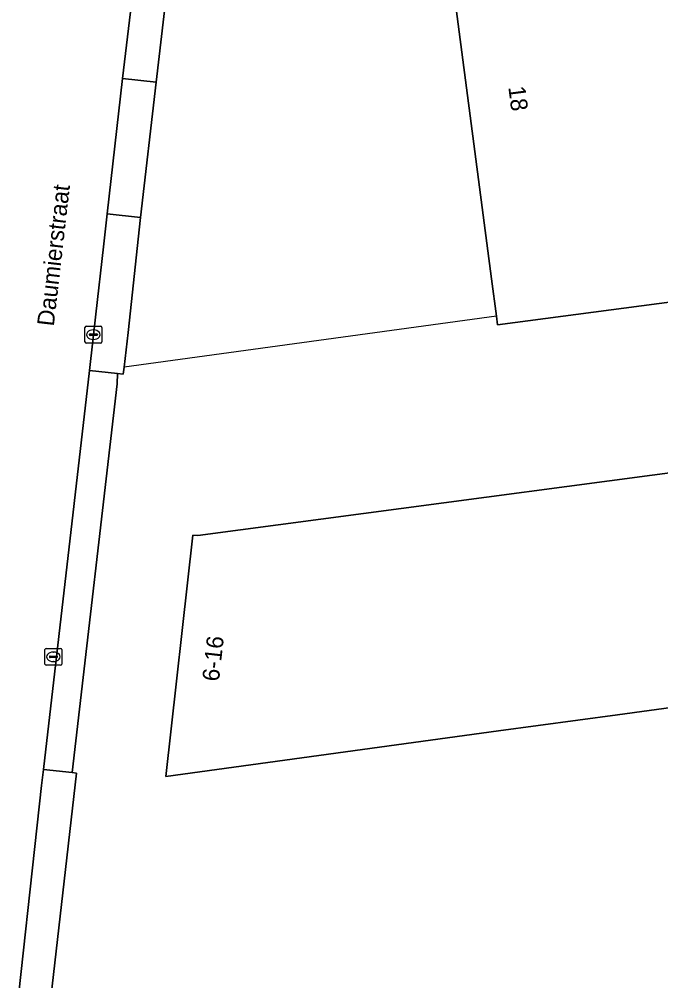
# Model space of a CAD drawing. Extents: x 160554 to 161248, y 385329 to 386506.
# Drawn here: x 161027.9 to 161065.9, y 385731.1 to 385787.9 of the extents above; entities that cross this region are included whole.
import ezdxf

# ---------------------------------------------------------------- set-up
doc = ezdxf.new("R2010")
doc.units = 0
for name, color, linetype in [('IMGEO_Erf', 7, 'Continuous'), ('IMGEO_Hek', 7, 'Continuous'), ('IMGEO_Kolk', 7, 'Continuous'), ('IMGEO_Openbare_ruimte_label', 7, 'Continuous'), ('IMGEO_Pand', 7, 'Continuous'), ('IMGEO_Pand_nummerreeks', 7, 'Continuous'), ('IMGEO_Rijbaan_lokaal_gesloten', 7, 'Continuous'), ('IMGEO_Voetpad_open', 7, 'Continuous')]:
    doc.layers.add(name, color=color, linetype=linetype)

msp = doc.modelspace()

# ---------------------------------------------------------------- linework, layer by layer
at = {"layer": 'IMGEO_Erf'}
for points in [[(161055.868, 385772.603), (161052.902, 385795.197), (161048.55, 385828.073), (161045.239, 385827.611), (161043.376, 385821.859)], [(161038.935, 385804.639), (161037.917, 385798.744), (161037.106, 385793.587), (161037.068, 385793.188), (161036.035, 385784.231), (161035.112, 385776.221), (161034.38, 385769.433), (161034.13, 385767.378), (161034.079, 385766.959), (161033.737, 385767.013), (161033.718, 385766.391), (161031.068, 385743.412), (161031.33, 385743.384), (161029.381, 385726.474), (161028.228, 385716.42), (161027.96, 385714.08)], [(161076.078, 385772.498), (161056.219, 385769.879), (161056.153, 385770.395), (161055.868, 385772.603)], [(161094.436, 385751.08), (161063.317, 385746.837), (161056.279, 385745.877), (161036.601, 385743.194), (161038.201, 385757.455), (161038.492, 385757.432), (161077.384, 385762.597)]]:
    msp.add_lwpolyline(points, dxfattribs=at)
at = {"layer": 'IMGEO_Hek'}
msp.add_lwpolyline([(161056.153, 385770.395), (161034.13, 385767.378)], dxfattribs=at)
at = {"layer": 'IMGEO_Kolk'}
for p, q in [((161031.821, 385768.871), (161031.821, 385769.723)), ((161031.896, 385769.797), (161032.748, 385769.797)), ((161032.08, 385769.291), (161032.08, 385769.303)), ((161032.518, 385769.254), (161032.12, 385769.254)), ((161032.123, 385769.34), (161032.521, 385769.34)), ((161032.309, 385769.577), (161032.334, 385769.577)), ((161032.564, 385769.303), (161032.564, 385769.291)), ((161032.822, 385769.723), (161032.822, 385768.871)), ((161032.748, 385768.797), (161031.896, 385768.797)), ((161032.332, 385769.017), (161032.307, 385769.017)), ((161029.456, 385749.833), (161029.456, 385750.685)), ((161029.531, 385750.759), (161030.383, 385750.759)), ((161029.944, 385750.539), (161029.969, 385750.539)), ((161030.457, 385750.685), (161030.457, 385749.833)), ((161029.715, 385750.253), (161029.715, 385750.265)), ((161030.153, 385750.216), (161029.755, 385750.216)), ((161029.758, 385750.302), (161030.156, 385750.302)), ((161029.967, 385749.979), (161029.942, 385749.979)), ((161030.199, 385750.265), (161030.199, 385750.253)), ((161030.383, 385749.759), (161029.531, 385749.759))]:
    msp.add_line(p, q, dxfattribs=at)
for points in [[(161031.821, 385768.871), (161031.821, 385769.723)], [(161031.896, 385769.797), (161032.748, 385769.797)], [(161032.822, 385769.723), (161032.822, 385768.871)], [(161032.748, 385768.797), (161031.896, 385768.797)], [(161029.456, 385749.833), (161029.456, 385750.685)], [(161029.531, 385750.759), (161030.383, 385750.759)], [(161030.457, 385750.685), (161030.457, 385749.833)], [(161030.383, 385749.759), (161029.531, 385749.759)]]:
    msp.add_lwpolyline(points, dxfattribs=at)
for centre, radius, start, end in [((161031.898, 385769.721), 0.0765, 91.552, 178.448), ((161031.898, 385769.721), 0.0765, 91.552, 178.448), ((161032.12, 385769.3), 0.0403, 85.8775, 175.7526), ((161032.117, 385769.29), 0.0366, 178.938, 274.7102), ((161032.521, 385769.297), 0.043, 264.8664, 352.4533), ((161032.525, 385769.302), 0.0386, 1.7309, 96.639), ((161032.746, 385769.721), 0.0765, 1.552, 88.448), ((161032.746, 385769.721), 0.0765, 1.552, 88.448), ((161031.898, 385768.873), 0.0765, 181.552, 268.448), ((161031.898, 385768.873), 0.0765, 181.552, 268.448), ((161032.746, 385768.873), 0.0765, 271.552, 358.448), ((161032.746, 385768.873), 0.0765, 271.552, 358.448), ((161029.533, 385750.683), 0.0765, 91.552, 178.448), ((161029.533, 385750.683), 0.0765, 91.552, 178.448), ((161030.381, 385750.683), 0.0765, 1.552, 88.448), ((161030.381, 385750.683), 0.0765, 1.552, 88.448), ((161029.755, 385750.262), 0.0403, 85.8775, 175.7526), ((161029.752, 385750.252), 0.0366, 178.938, 274.7102), ((161030.156, 385750.259), 0.043, 264.8664, 352.4533), ((161030.16, 385750.264), 0.0386, 1.7309, 96.639), ((161029.533, 385749.835), 0.0765, 181.552, 268.448), ((161029.533, 385749.835), 0.0765, 181.552, 268.448), ((161030.381, 385749.835), 0.0765, 271.552, 358.448), ((161030.381, 385749.835), 0.0765, 271.552, 358.448)]:
    msp.add_arc(centre, radius, start, end, dxfattribs=at)
for centre, major_axis, ratio, start_param, end_param in [((161032.308, 385769.297), (-0.387, 0.002), 0.722429, 4.712389, 7.853982), ((161032.333, 385769.297), (-0.39, 0.002), 0.717154, 1.570796, 4.712389), ((161029.943, 385750.259), (-0.387, 0.002), 0.722429, 4.712389, 7.853982), ((161029.968, 385750.259), (-0.39, 0.002), 0.717154, 1.570796, 4.712389)]:
    msp.add_ellipse(centre, major_axis=major_axis, ratio=ratio, start_param=start_param, end_param=end_param, dxfattribs=at)
at = {"layer": 'IMGEO_Pand'}
for points in [[(161076.078, 385772.498), (161076.047, 385772.874), (161091.316, 385774.876), (161088.156, 385799.689), (161087.153, 385799.563), (161052.902, 385795.197), (161055.868, 385772.603), (161056.153, 385770.395), (161056.219, 385769.879)], [(161076.078, 385772.498), (161077.384, 385762.597), (161038.492, 385757.432), (161038.201, 385757.455), (161036.601, 385743.194), (161056.279, 385745.877), (161063.317, 385746.837), (161094.436, 385751.08), (161094.334, 385751.863), (161091.407, 385774.182), (161091.316, 385774.876), (161076.047, 385772.874)]]:
    msp.add_lwpolyline(points, close=True, dxfattribs=at)
at = {"layer": 'IMGEO_Rijbaan_lokaal_gesloten'}
msp.add_lwpolyline([(161026.519, 385716.608), (161026.919, 385721.569), (161026.935, 385721.716), (161027.49, 385726.612), (161029.258, 385742.653), (161029.367, 385743.592), (161032.084, 385767.18), (161032.459, 385770.514), (161032.911, 385774.499), (161033.133, 385776.441), (161034.05, 385784.434), (161034.993, 385792.349), (161035.902, 385799.081)], dxfattribs=at)
at = {"layer": 'IMGEO_Voetpad_open'}
for points in [[(161037.068, 385793.188), (161037.106, 385793.587), (161037.917, 385798.744), (161035.902, 385799.081), (161034.993, 385792.349), (161034.05, 385784.434), (161036.035, 385784.231)], [(161034.05, 385784.434), (161033.133, 385776.441), (161035.112, 385776.221), (161036.035, 385784.231)], [(161033.133, 385776.441), (161032.911, 385774.499), (161032.459, 385770.514), (161032.084, 385767.18), (161033.737, 385767.013), (161034.079, 385766.959), (161034.13, 385767.378), (161034.38, 385769.433), (161035.112, 385776.221)], [(161033.737, 385767.013), (161032.084, 385767.18), (161029.367, 385743.592), (161031.068, 385743.412), (161033.718, 385766.391)], [(161029.367, 385743.592), (161029.258, 385742.653), (161027.49, 385726.612), (161029.381, 385726.474), (161031.33, 385743.384), (161031.068, 385743.412)]]:
    msp.add_lwpolyline(points, close=True, dxfattribs=at)

# ---------------------------------------------------------------- texts
at = {"layer": 'IMGEO_Openbare_ruimte_label'}
msp.add_text('Daumierstraat', height=1, rotation=83.4574, dxfattribs=at).set_placement((161029.978, 385769.766))
at = {"layer": 'IMGEO_Pand_nummerreeks'}
for s, rotation, p in [('18', 277.236, (161056.855, 385783.937)), ('6-16', 83.5985, (161039.742, 385748.772))]:
    msp.add_text(s, height=1, rotation=rotation, dxfattribs=at).set_placement(p)

doc.saveas('drawing.dxf')
